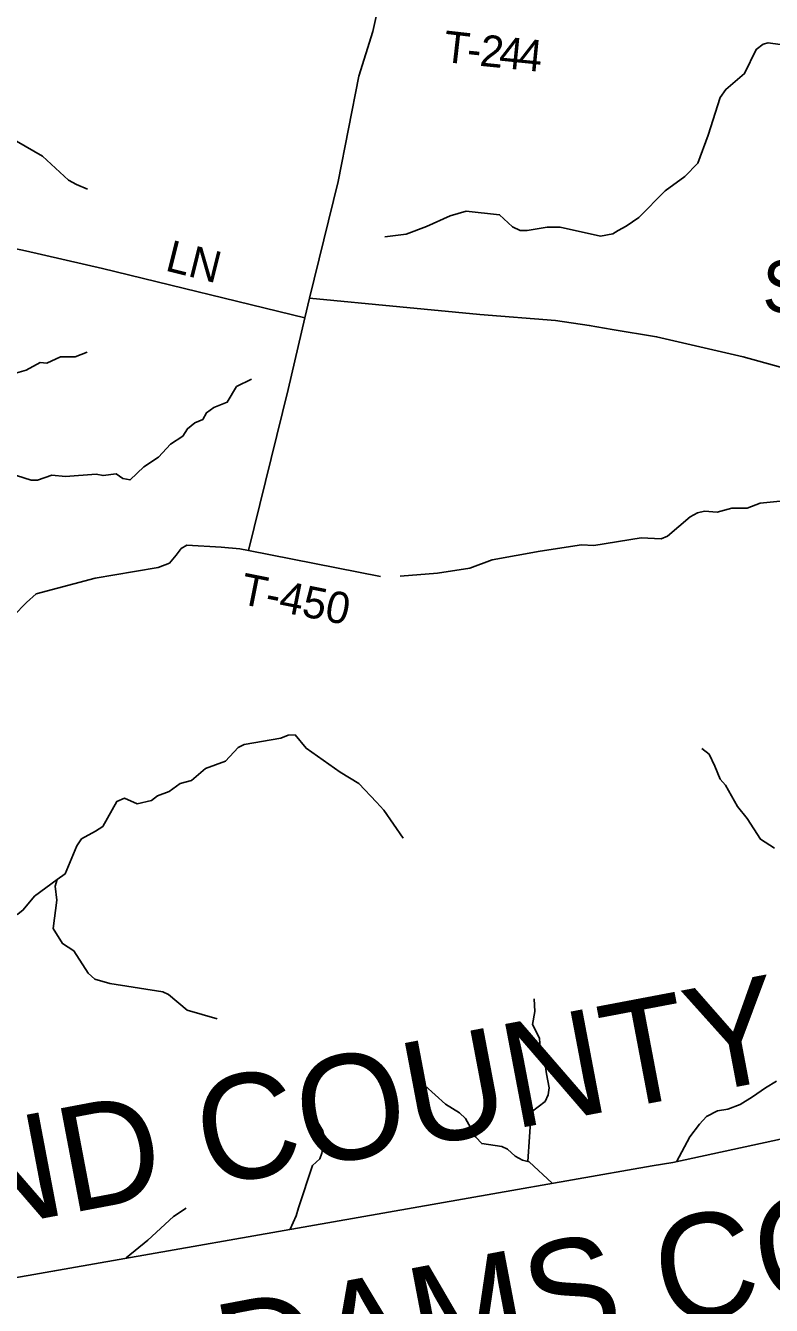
# Model space of a CAD drawing. Extents: x 0 to 34, y 0 to 22.
# Drawn here: x 3.854 to 5.2, y 14.612 to 16.923 of the extents above; entities that cross this region are included whole.
import ezdxf

# ---------------------------------------------------------------- set-up
doc = ezdxf.new("R2010")
doc.units = 0
for name, color, linetype in [('GM_X_Adjacent_County', 7, 'Continuous'), ('GM_X_Adjacent_County_Text', 7, 'Continuous'), ('GM_X_Corporation_Text', 7, 'Continuous'), ('GM_X_County_Road', 7, 'Continuous'), ('GM_X_Minor_River', 7, 'Continuous'), ('GM_X_Township_Road', 7, 'Continuous'), ('GM_X_Township_Road_Text', 7, 'Continuous')]:
    doc.layers.add(name, color=color, linetype=linetype)

msp = doc.modelspace()

# ---------------------------------------------------------------- linework, layer by layer
at = {"layer": 'GM_X_Adjacent_County'}
msp.add_lwpolyline([(9.4, 14.9965), (8.815, 15.0315), (8.2967, 15.0626), (8.1206, 15.0731), (7.1103, 15.1434), (6.9032, 15.1545), (6.5214, 15.204), (6.1992, 15.1249), (5.0219, 14.8699), (4.9843, 14.8636), (3.402, 14.5859), (3.2736, 14.5654), (2.6, 14.46)], dxfattribs=at)
at = {"layer": 'GM_X_County_Road'}
msp.add_lwpolyline([(4.5003, 17.0015), (4.4801, 16.9118), (4.4552, 16.8312), (4.4177, 16.6408), (4.366, 16.4302), (4.5292, 16.4149), (4.6734, 16.4006), (4.8099, 16.39), (4.8707, 16.3813), (4.9124, 16.3739), (4.9925, 16.3608), (5.1486, 16.3245), (5.2333, 16.3007)], dxfattribs=at)
at = {"layer": 'GM_X_Minor_River'}
for points in [[(5.2669, 16.8809), (5.194, 16.8911), (5.1845, 16.8889), (5.1719, 16.8796), (5.1511, 16.8358), (5.1171, 16.8074), (5.1071, 16.7927), (5.0853, 16.7247), (5.0666, 16.6741), (5.0433, 16.65), (5.0078, 16.6239), (4.9605, 16.5758), (4.9372, 16.5601), (4.9232, 16.5527), (4.9133, 16.5467), (4.8913, 16.5424), (4.8184, 16.5583), (4.7946, 16.5585), (4.759, 16.5528), (4.7461, 16.5526), (4.7325, 16.5591), (4.7089, 16.581), (4.6488, 16.5876), (4.62, 16.5792), (4.577, 16.5599), (4.5402, 16.5459), (4.502, 16.541)], [(3.837, 16.7139), (3.8841, 16.6869), (3.9313, 16.6436), (3.9452, 16.6359), (3.9652, 16.6274)], [(3.7073, 16.1046), (3.7103, 16.1425), (3.7179, 16.178), (3.7111, 16.2213), (3.7173, 16.2709), (3.7193, 16.283), (3.7307, 16.2874), (3.7427, 16.2828), (3.778, 16.2896), (3.7908, 16.2853), (3.8037, 16.286), (3.8549, 16.3002), (3.88, 16.314), (3.8917, 16.3128), (3.9168, 16.3243), (3.9429, 16.3244), (3.9649, 16.3329)], [(3.8375, 16.1102), (3.8639, 16.1016), (3.8753, 16.1018), (3.9011, 16.1107), (3.9256, 16.1082), (3.9809, 16.1125), (3.9934, 16.1102), (4.0172, 16.1133), (4.0289, 16.1049), (4.0421, 16.1021), (4.0669, 16.1257), (4.0932, 16.1433), (4.1154, 16.1666), (4.1371, 16.1815), (4.1456, 16.1947), (4.1589, 16.2055), (4.1733, 16.2115), (4.1799, 16.2235), (4.1932, 16.2329), (4.2175, 16.2429), (4.2345, 16.2707), (4.2611, 16.2841)], [(5.2153, 16.064), (5.179, 16.0602), (5.1558, 16.0513), (5.1422, 16.0514), (5.1282, 16.0512), (5.1016, 16.0439), (5.079, 16.0456), (5.0661, 16.0427), (5.0531, 16.0356), (5.0123, 16.0004), (5.0009, 15.9956), (4.9646, 15.9979), (4.879, 15.9839), (4.857, 15.9853), (4.7824, 15.9735), (4.6956, 15.9581), (4.6553, 15.9429), (4.597, 15.934), (4.5296, 15.9286)], [(3.9109, 15.3808), (3.925, 15.3912), (3.9459, 15.4418), (3.9548, 15.4545), (3.9799, 15.4679), (3.9928, 15.4762), (4.0182, 15.5214), (4.0319, 15.5277), (4.0549, 15.5176), (4.0807, 15.5234), (4.0914, 15.532), (4.113, 15.5394), (4.1328, 15.5544), (4.1533, 15.5595), (4.1785, 15.5812), (4.2142, 15.5945), (4.2375, 15.6193), (4.2478, 15.6245), (4.3141, 15.6359), (4.3274, 15.6411), (4.3399, 15.6418), (4.3597, 15.6177), (4.4213, 15.5746), (4.4548, 15.5542), (4.4866, 15.5206), (4.5001, 15.506), (4.5352, 15.4553)], [(5.2053, 15.4375), (5.1801, 15.4534), (5.156, 15.4912), (5.1381, 15.5123), (5.117, 15.5513), (5.1069, 15.562), (5.0974, 15.5857), (5.087, 15.607), (5.0739, 15.6174)], [(3.3589, 15.1148), (3.3734, 15.162), (3.3918, 15.1869), (3.4161, 15.201), (3.4558, 15.1949), (3.4899, 15.1999), (3.5306, 15.2166), (3.5772, 15.2241), (3.6683, 15.2523), (3.7649, 15.2711), (3.7851, 15.2796), (3.8152, 15.3096), (3.8395, 15.3181), (3.8495, 15.326), (3.8698, 15.3508), (3.9109, 15.3808)], [(3.9109, 15.3808), (3.907, 15.3686), (3.9098, 15.3436), (3.9036, 15.2925), (3.9204, 15.265), (3.9407, 15.2519), (3.9664, 15.2119), (3.9788, 15.2008), (4.0059, 15.1933), (4.1011, 15.178), (4.1113, 15.1729), (4.1454, 15.1446), (4.1994, 15.1293)], [(4.76, 14.8716), (4.7661, 14.9605), (4.791, 14.9802), (4.7969, 14.9923), (4.7986, 15.0048), (4.7936, 15.0302), (4.7909, 15.0508), (4.7825, 15.0748), (4.7813, 15.0945), (4.7687, 15.119), (4.7725, 15.1424), (4.7717, 15.1656)], [(4.5524, 15.0651), (4.5743, 15.0087), (4.6114, 14.9751), (4.6365, 14.9596), (4.6478, 14.9492), (4.6662, 14.9156), (4.6767, 14.9041), (4.713, 14.899), (4.7231, 14.8939), (4.737, 14.8812), (4.7501, 14.8738), (4.7626, 14.871), (4.8038, 14.8325)], [(4.36, 14.962), (4.3809, 14.9419), (4.3898, 14.927), (4.3931, 14.9148), (4.3885, 14.8865), (4.3846, 14.8763), (4.3711, 14.8643), (4.3462, 14.7877), (4.3422, 14.7737), (4.331, 14.7497)], [(4.1435, 14.7875), (4.1205, 14.7722), (4.0745, 14.7296), (4.0352, 14.698)]]:
    msp.add_lwpolyline(points, dxfattribs=at)
at = {"layer": 'GM_X_Township_Road'}
for points in [[(3.3418, 16.6396), (3.3482, 16.638), (3.4669, 16.6089), (3.5849, 16.5759), (3.7215, 16.5433), (3.8532, 16.5156), (3.9924, 16.4841), (4.3578, 16.3948)], [(3.832, 15.8569), (3.855, 15.881), (3.8727, 15.8966), (3.9791, 15.925), (4.0499, 15.9368), (4.0931, 15.9443), (4.1132, 15.952), (4.1252, 15.9661), (4.1346, 15.9783), (4.1448, 15.9844), (4.2063, 15.9806), (4.2404, 15.9778), (4.2557, 15.975), (4.3276, 16.2656), (4.3578, 16.3948), (4.366, 16.4302)], [(4.2557, 15.975), (4.4942, 15.9278)], [(5.0284, 14.871), (5.0524, 14.9164), (5.0697, 14.9393), (5.0825, 14.9526), (5.1025, 14.9634), (5.1211, 14.9662), (5.143, 14.9746), (5.1653, 14.9884), (5.1891, 15.0049), (5.2087, 15.0164)]]:
    msp.add_lwpolyline(points, dxfattribs=at)

# ---------------------------------------------------------------- texts
at = {"layer": 'GM_X_Adjacent_County_Text'}
for s, p in [('HIGHLAND COUNTY', (2.8262, 14.568)), ('ADAMS COUNTY', (4.054, 14.3918))]:
    msp.add_text(s, height=0.189394, rotation=10.7426, dxfattribs=at).set_placement(p)
at = {"layer": 'GM_X_Corporation_Text'}
msp.add_text('SINKING SPRING', height=0.094697, rotation=0, dxfattribs=at).set_placement((5.1831, 16.4042))
at = {"layer": 'GM_X_Township_Road_Text'}
for s, height, rotation, p in [('T', 0.0568, 353.4804, (4.6054, 16.8574)), ('2', 0.0568, 354.2559, (4.6717, 16.8501)), ('4', 0.0568, 354.2837, (4.7065, 16.8466)), ('4', 0.0568, 354.288, (4.7414, 16.8431)), ('-', 0.0568, 354.1339, (4.6483, 16.8525)), ('LN', 0.05682, 345.9638, (4.1036, 16.4808)), ('T-450', 0.05682, 348.6899, (4.238, 15.879))]:
    msp.add_text(s, height=height, rotation=rotation, dxfattribs=at).set_placement(p)

doc.saveas('drawing.dxf')
